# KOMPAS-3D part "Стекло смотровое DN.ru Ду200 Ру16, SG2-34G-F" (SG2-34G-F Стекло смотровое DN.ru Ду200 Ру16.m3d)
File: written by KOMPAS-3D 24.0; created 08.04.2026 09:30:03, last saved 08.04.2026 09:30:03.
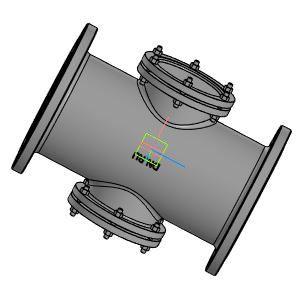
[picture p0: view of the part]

Document properties: Автор: Main; Полное имя файла: D:\DN.ru Аутсерс\Стекло смотровое DN.ru\SG2-34G-F Стекло смотровое DN.ru Ду200 Ру16\SG2-34G-F Стекло смотровое DN.ru Ду200 Ру16.m3d

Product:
- Part/product: Стекло смотровое DN.ru Ду200 Ру16  | designation SG2-34G-F
    Масса: 55
    Раздел спецификации: Прочие изделия
    Примечание: D500-00090

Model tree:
1. Операция без истории:1

Expressions: SG2-34G-F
